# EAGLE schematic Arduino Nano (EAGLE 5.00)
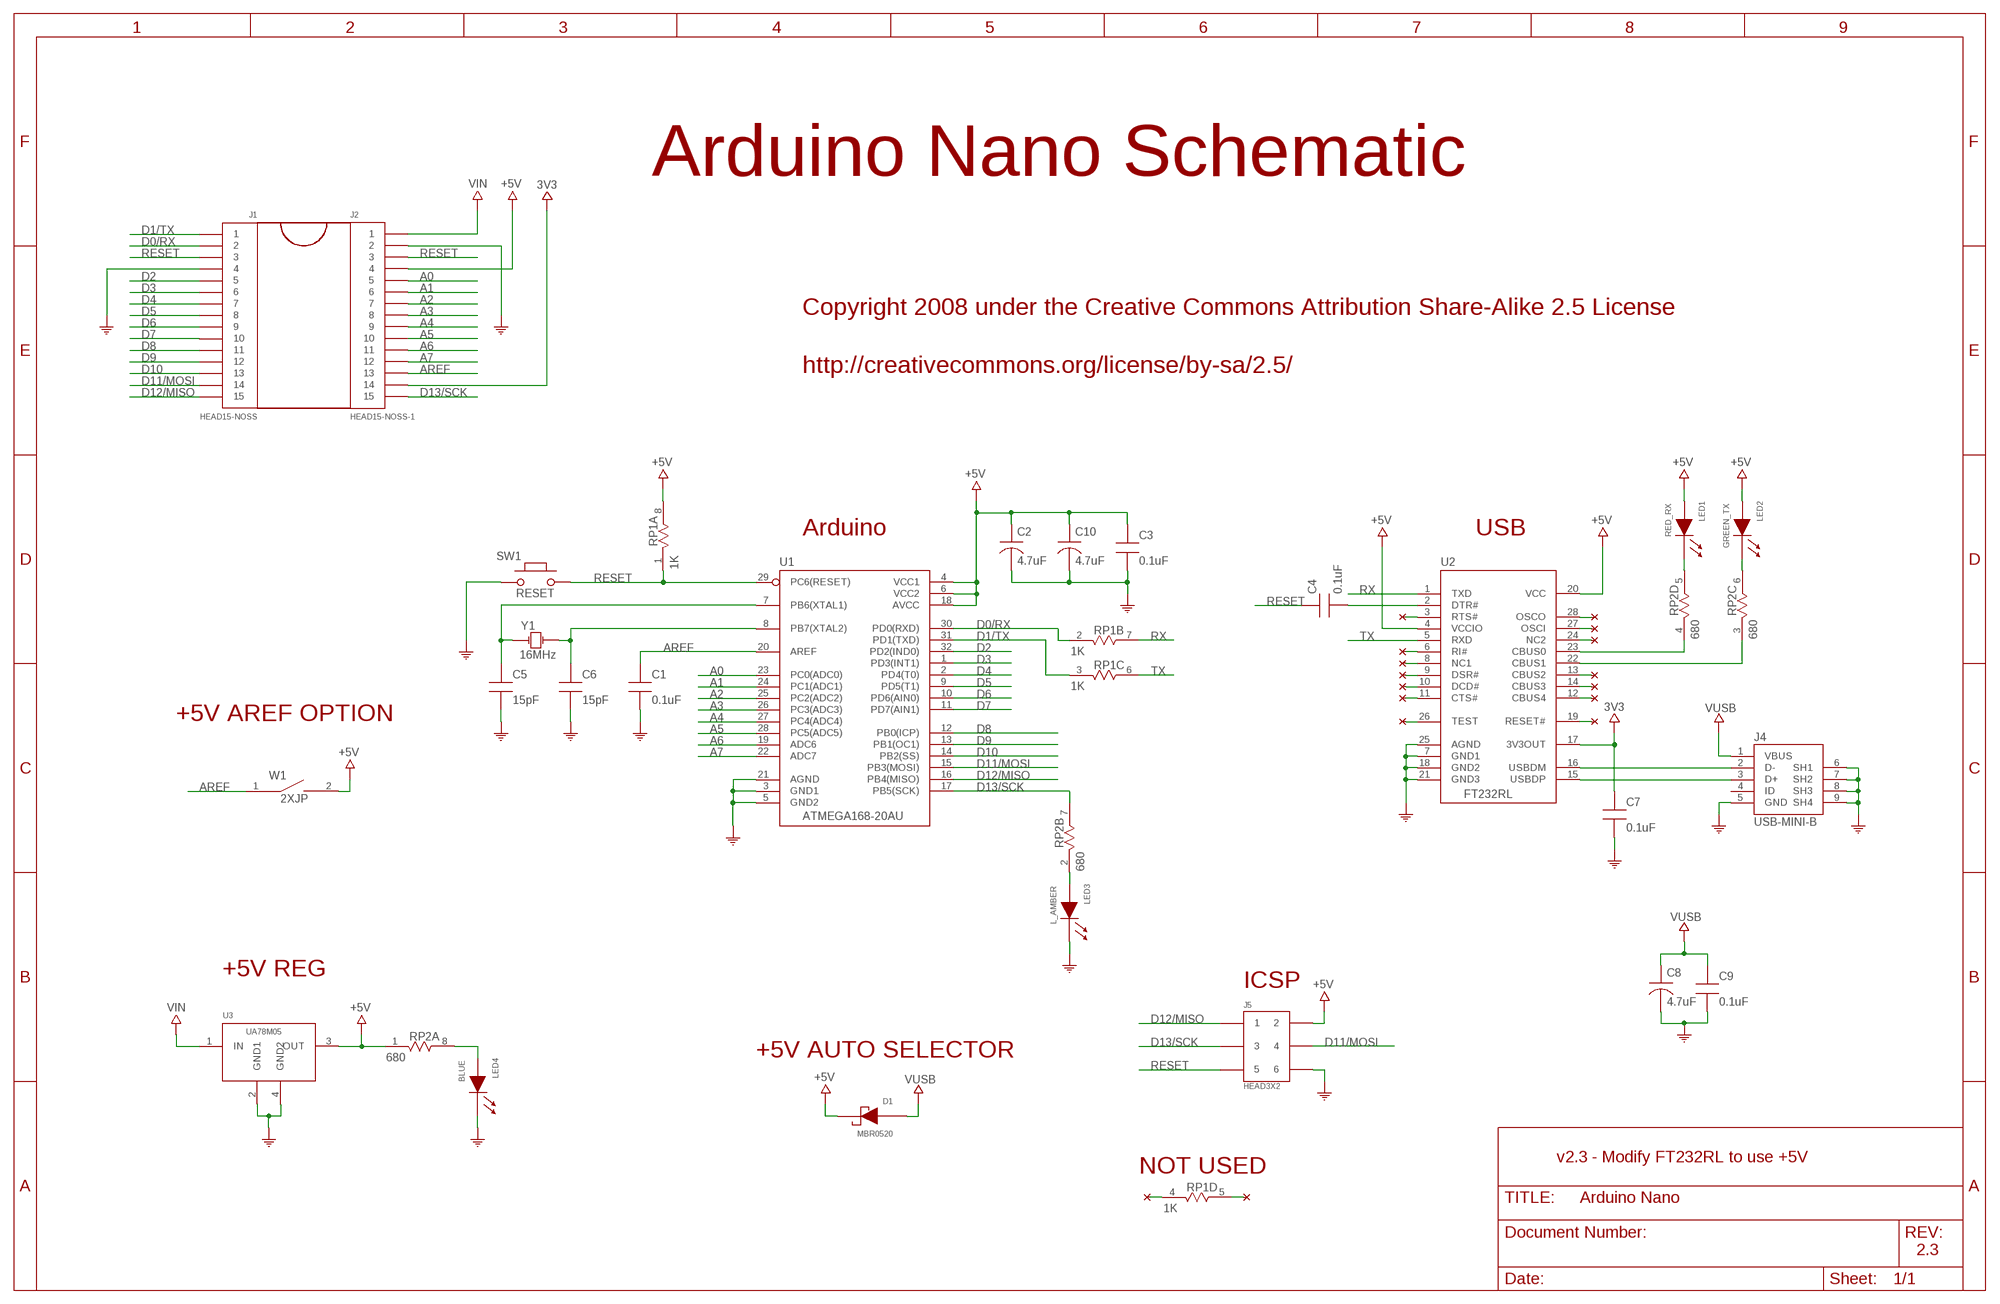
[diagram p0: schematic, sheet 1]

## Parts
C1  0.1uF  CAP0805-NP  [CAP0805-NP]
C2  4.7uF  CAP-TANA-P  [TAN-A]
C3  0.1uF  CAP0805-NP  [CAP0805-NP]
C4  0.1uF  CAP0805-NP  [CAP0805-NP]
C5  15pF  CAP0805-NP  [CAP0805-NP]
C6  15pF  CAP0805-NP  [CAP0805-NP]
C7  0.1uF  CAP0805-NP  [CAP0805-NP]
C8  4.7uF  CAP-TANA-P  [TAN-A]
C9  0.1uF  CAP0805-NP  [CAP0805-NP]
C10  4.7uF  CAP-TANA-P  [TAN-A]
D1  MBR0520  [SOD-123]
J1  HEAD15-NOSS  [HEAD15-NOSS]
J2  HEAD15-NOSS-1  [HEAD15-NOSS-1]
J4  USB-MINI-B  [USB-MINI-B]
J5  HEAD3X2  [HEAD3X2]
LED1  RED_RX  LED0805  [LED0805]
LED2  GREEN_TX  LED0805  [LED0805]
LED3  L_AMBER  LED0805  [LED0805]
LED4  BLUE  LED0805  [LED0805]
RP1  1K  RES4NT  [RES4NT]
RP2  680  RES4NT  [RES4NT]
SW1  RESET  PB157  [157SW]
U1  ATMEGA168-20AU  [QFP032]
U2  FT232RL  [SSOP28]
U3  UA78M05  [SOT223]
W1  2XJP  [2JP]
Y1  16MHz  CRYSTAL-TH  [CRYSTAL-TH]

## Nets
3V3: C7.1 J2.14 U2.17(3V3OUT)
+5V: C2.1 C3.1 C10.1 D1.1(CA) J2.4 J5.2 LED1.2(AN) LED2.2(AN) RP1.8 RP2.1 U1.4(VCC1) U1.6(VCC2) U1.18(AVCC) U2.4(VCCIO) U2.20(VCC) U3.3(OUT) W1.2
A0: J2.5 U1.23(PC0(ADC0))
A1: J2.6 U1.24(PC1(ADC1))
A2: J2.7 U1.25(PC2(ADC2))
A3: J2.8 U1.26(PC3(ADC3))
A4: J2.9 U1.27(PC4(ADC4))
A5: J2.10 U1.28(PC5(ADC5))
A6: J2.11 U1.19(ADC6)
A7: J2.12 U1.22(ADC7)
AREF: C1.1 J2.13 U1.20(AREF) W1.1
COM: C1.2 C2.2 C3.2 C5.2 C6.2 C7.2 C8.2 C9.2 C10.2 J1.4 J2.2 J4.5(GND) J4.6(SH1) J4.7(SH2) J4.8(SH3) J4.9(SH4) J5.6 LED3.1(CA) LED4.1(CA) SW1.1 U1.3(GND1) U1.5(GND2) U1.21(AGND) U2.7(GND1) U2.18(GND2) U2.21(GND3) U2.25(AGND) U3.2(GND1) U3.4(GND2)
D0/RX: J1.2 RP1.2 U1.30(PD0(RXD))
D1/TX: J1.1 RP1.3 U1.31(PD1(TXD))
D2: J1.5 U1.32(PD2(IND0))
D3: J1.6 U1.1(PD3(INT1))
D4: J1.7 U1.2(PD4(T0))
D5: J1.8 U1.9(PD5(T1))
D6: J1.9 U1.10(PD6(AIN0))
D7: J1.10 U1.11(PD7(AIN1))
D8: J1.11 U1.12(PB0(ICP))
D9: J1.12 U1.13(PB1(OC1))
D10: J1.13 U1.14(PB2(SS))
D11/MOSI: J1.14 J5.4 U1.15(PB3(MOSI))
D12/MISO: J1.15 J5.1 U1.16(PB4(MISO))
D13/SCK: J2.15 J5.3 RP2.7 U1.17(PB5(SCK))
N$1: C6.1 U1.8(PB7(XTAL2)) Y1.2
N$2: C5.1 U1.7(PB6(XTAL1)) Y1.1
N$3: LED4.2(AN) RP2.8
N$4: C4.2 U2.2(DTR#)
N$5: J4.3(D+) U2.15(USBDP)
N$6: J4.2(D-) U2.16(USBDM)
N$7: LED3.2(AN) RP2.2
N$8: RP2.4 U2.23(CBUS0)
N$9: RP2.3 U2.22(CBUS1)
N$10: LED1.1(CA) RP2.5
N$11: LED2.1(CA) RP2.6
N$12: U2.11(CTS#)
N$13: U2.6(RI#)
N$14: U2.8(NC1)
N$15: U2.9(DSR#)
N$16: U2.10(DCD#)
N$17: U2.28(OSCO)
N$18: U2.27(OSCI)
N$19: U2.24(NC2)
N$20: U2.13(CBUS2)
N$21: U2.14(CBUS3)
N$22: U2.12(CBUS4)
N$23: U2.19(RESET#)
N$24: RP1.4
N$25: RP1.5
N$26: U2.26(TEST)
N$27: U2.3(RTS#)
RESET: C4.1 J1.3 J2.3 J5.5 RP1.1 SW1.2 U1.29(PC6(RESET))
RX: RP1.7 U2.1(TXD)
TX: RP1.6 U2.5(RXD)
VIN: J2.1 U3.1(IN)
VUSB: C8.1 C9.1 D1.2(AN) J4.1(VBUS)
Unconnected: J4.4(ID)

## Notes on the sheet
- Arduino Nano Schematic
- Copyright 2008 under the Creative Commons Attribution Share-Alike 2.5 License
- http://creativecommons.org/license/by-sa/2.5/
- Arduino | USB
- +5V AREF OPTION
- +5V REG
- ICSP
- +5V AUTO SELECTOR
- v2.3 - Modify FT232RL to use +5V
- NOT USED
- 2.3

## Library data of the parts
C1 C3-C7 C9 = MySMD:CAP0805-NP
C2 C8 C10 = MySMD:CAP-TANA-P
D1 = MySMD:MBR0520
J1 = MyCON:HEAD15-NOSS
J2 = MyCON:HEAD15-NOSS-1
J4 = MyCON:USB-MINI-B
J5 = MyCON:HEAD3X2
LED1-LED4 = MySMD:LED0805
RP1 RP2 = MySMD:RES4NT
SW1 = MySMD:PB157
U1 = MySMD:ATMEGA168-20AU
U2 = MySMD:FT232RL
U3 = MySMD:UA78M05
W1 = MySMD:2XJP
Y1 = MyTHR:CRYSTAL-TH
